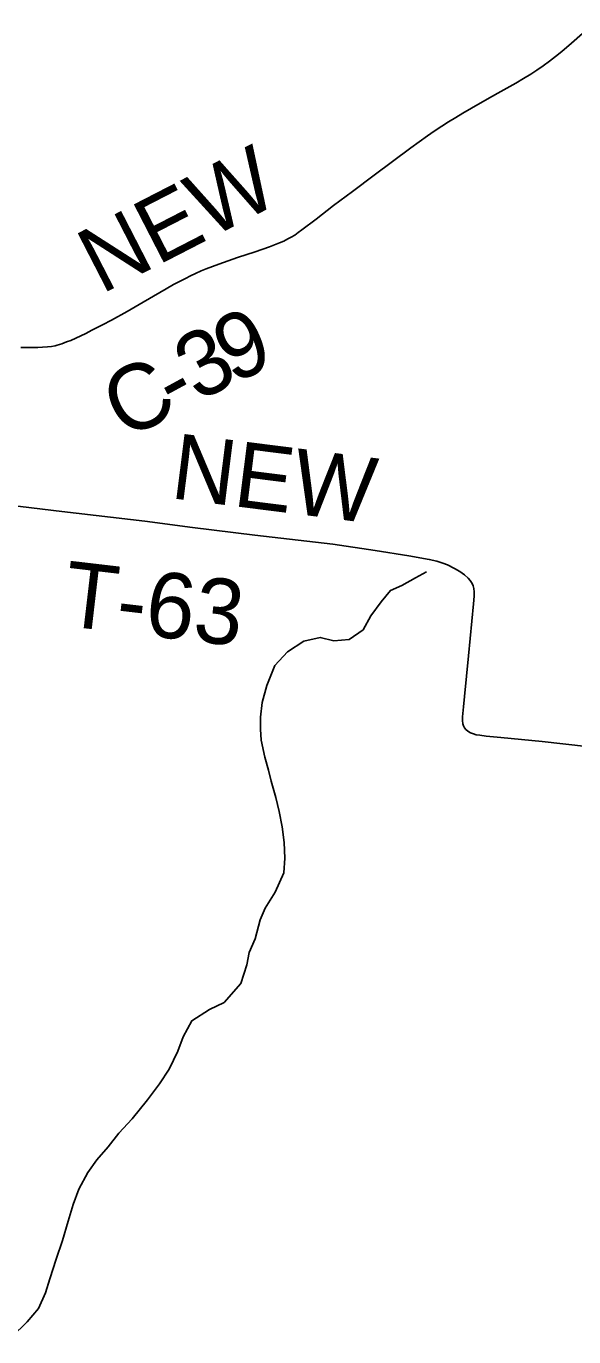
# Model space of a CAD drawing. Extents: x 1451455 to 1749751, y 218250 to 574981.
# Drawn here: x 1568019 to 1570534, y 349922 to 355937 of the extents above; entities that cross this region are included whole.
import ezdxf

# ---------------------------------------------------------------- set-up
doc = ezdxf.new("R2010")
doc.units = 0
for name, color, linetype in [('GM_X_County_Road', 7, 'Continuous'), ('GM_X_County_Road_Text', 7, 'Continuous'), ('GM_X_Minor_River', 7, 'Continuous'), ('GM_X_Township_Road', 7, 'Continuous'), ('GM_X_Township_Road_Text', 7, 'Continuous')]:
    doc.layers.add(name, color=color, linetype=linetype)

msp = doc.modelspace()

# ---------------------------------------------------------------- linework, layer by layer
at = {"layer": 'GM_X_County_Road'}
msp.add_lwpolyline([(1567993.9, 354462.8), (1568028.6, 354462.8), (1568072.8, 354463.6), (1568093.7, 354464.5), (1568117.1, 354466.3), (1568135.6, 354468.2), (1568151.6, 354470.8), (1568160.7, 354473), (1568171.6, 354476), (1568182.5, 354479.9), (1568205, 354488.2), (1568223.9, 354495.7), (1568246.5, 354506.2), (1568269.9, 354516.6), (1568292.5, 354527.9), (1568320.3, 354541.9), (1568369.7, 354567.3), (1568410.4, 354588.4), (1568482.5, 354627.7), (1568556.6, 354670.3), (1568632.8, 354715.5), (1568661.4, 354731.9), (1568695.3, 354751.3), (1568750.2, 354780.3), (1568773.4, 354791.7), (1568796.8, 354803.1), (1568822.8, 354814.3), (1568845.4, 354823.5), (1568903.4, 354845.6), (1568990.1, 354875.4), (1569071.3, 354901.7), (1569136.6, 354924.3), (1569182.6, 354942.6), (1569202.2, 354951.5), (1569221.3, 354961.3), (1569236.9, 354969.7), (1569252.5, 354979.2), (1569268.2, 354990.6), (1569285, 355002.6), (1569350.6, 355052.1), (1569431.3, 355113.9), (1569517.8, 355179), (1569617, 355254.4), (1569785.5, 355379.5), (1569862.9, 355434.6), (1569893.2, 355455.8), (1569928, 355478.6), (1569959.1, 355498.4), (1569991.7, 355518.8), (1570024.3, 355538.3), (1570065, 355562.1), (1570136.3, 355602.3), (1570185, 355629.5), (1570267.6, 355676.7), (1570303.7, 355698), (1570337.6, 355718), (1570364.5, 355735.3), (1570392.8, 355755.6), (1570421.9, 355777.1), (1570450.5, 355798.7), (1570478.9, 355821.7), (1570524.3, 355859.7), (1570613.2, 355937.5)], dxfattribs=at)
at = {"layer": 'GM_X_Minor_River'}
msp.add_lwpolyline([(1567952.8, 349922.5), (1568024, 349991.6), (1568075.1, 350052.9), (1568108.4, 350124.6), (1568127.5, 350188.5), (1568157, 350278.2), (1568186.5, 350364), (1568212.1, 350453.8), (1568235.4, 350529.7), (1568260.6, 350599.4), (1568301.9, 350677), (1568342.9, 350734.5), (1568396, 350793.8), (1568445.1, 350857.2), (1568506.3, 350922.4), (1568575.8, 351009.6), (1568631.1, 351082.9), (1568676.3, 351150.3), (1568715.8, 351233.9), (1568740.9, 351299.7), (1568780.2, 351373.3), (1568861.1, 351424.1), (1568927.7, 351457.2), (1569005.3, 351544.2), (1569032.8, 351630), (1569043.7, 351685.9), (1569070.8, 351749.6), (1569094.2, 351835.5), (1569117.2, 351889.2), (1569162.4, 351962.7), (1569202, 352052.3), (1569207.1, 352118.4), (1569204.3, 352190.6), (1569195.5, 352262.9), (1569180.6, 352333.3), (1569165.7, 352397.7), (1569144.9, 352472.2), (1569131.7, 352522.5), (1569114.7, 352582.9), (1569098, 352661.4), (1569094.8, 352711.5), (1569095.7, 352765.7), (1569102.8, 352833.7), (1569124.1, 352911.6), (1569161.7, 353003.2), (1569218.8, 353066.4), (1569293.7, 353115.4), (1569370, 353132.2), (1569431.9, 353117.2), (1569502, 353122.1), (1569566.8, 353167.2), (1569601.9, 353230.8), (1569649, 353296.2), (1569691.9, 353347.6), (1569744.4, 353370.8), (1569807, 353405.9), (1569857.5, 353433.2)], dxfattribs=at)
at = {"layer": 'GM_X_Township_Road'}
msp.add_lwpolyline([(1567890, 353745.4), (1568183.2, 353710.1), (1568564.4, 353665.4), (1568782.3, 353636.7), (1569069, 353602.2), (1569427.4, 353559.6), (1569622, 353531.5), (1569777.3, 353506.6), (1569870.7, 353490.4), (1569905.6, 353482.1), (1569932.5, 353473.8), (1569954, 353465.2), (1569985.9, 353449.2), (1570010.9, 353434.3), (1570031.9, 353419.3), (1570048.6, 353404.6), (1570059, 353392.8), (1570067.5, 353379.8), (1570072.3, 353368.7), (1570075.3, 353356.7), (1570076.9, 353341), (1570076.6, 353321.8), (1570073.2, 353286.2), (1570050.2, 353047.7), (1570032.6, 352861.9), (1570027.3, 352813.2), (1570024.1, 352783.6), (1570022.8, 352767.7), (1570022.8, 352750.7), (1570024.4, 352736.2), (1570027.6, 352726), (1570032.3, 352716.8), (1570038.9, 352709.1), (1570048, 352701.3), (1570059.3, 352694.7), (1570073.4, 352689.3), (1570086.1, 352685.7), (1570103.2, 352683), (1570131, 352679.8), (1570199.7, 352672.5), (1570388.6, 352654.8), (1570796, 352608.6)], dxfattribs=at)

# ---------------------------------------------------------------- texts
at = {"layer": 'GM_X_County_Road_Text'}
for s, rotation, p in [('NEW', 27.22389, (1568364, 354705.3)), ('9', 23.65813, (1568965.7, 354295.2)), ('3', 28.20947, (1568808.5, 354210.6)), ('C', 26.39225, (1568469.2, 354037)), ('-', 28.48009, (1568700.6, 354152))]:
    msp.add_text(s, height=300, rotation=rotation, dxfattribs=at).set_placement(p)
at = {"layer": 'GM_X_Township_Road_Text'}
for s, rotation, p in [('NEW', 352.80064, (1568676.3, 353772.3)), ('T-63', 353.3112, (1568180.2, 353186.8))]:
    msp.add_text(s, height=300, rotation=rotation, dxfattribs=at).set_placement(p)

doc.saveas('drawing.dxf')
